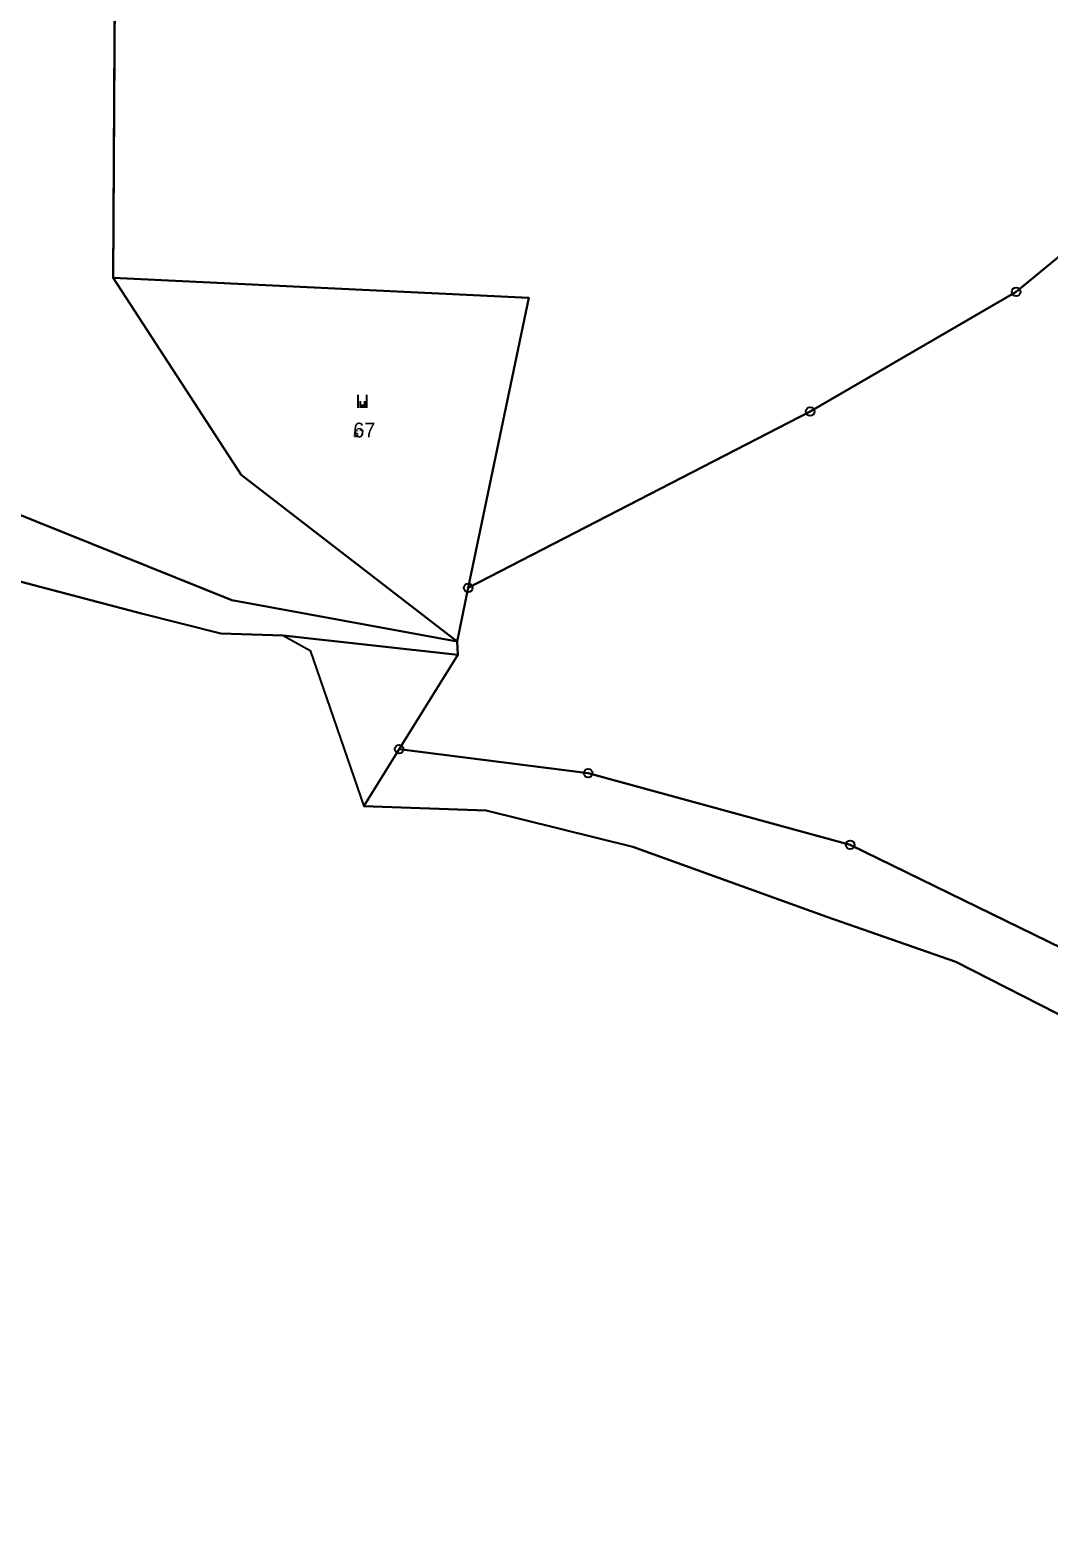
# Model space of a CAD drawing. Extents: x -759873 to -758487, y -975024 to -973516.
# Drawn here: x -759264.7 to -759147.2, y -974042.3 to -973868.5 of the extents above; entities that cross this region are included whole.
import ezdxf

# ---------------------------------------------------------------- set-up
doc = ezdxf.new("R2010")
doc.units = 0
for name, color, linetype in [('KAT_02_hranice parcel', 7, 'Continuous'), ('KAT_03_1000_čísla parcelní', 7, 'Continuous'), ('KAT_03_250_čísla parcelní', 7, 'Continuous'), ('KAT_03_500_čísla parcelní', 7, 'Continuous'), ('KAT_04_vnitřní kresba', 7, 'Continuous'), ('KAT_05_1000_značky kultur', 7, 'Continuous'), ('KAT_05_250_značky kultur', 7, 'Continuous'), ('KAT_05_500_značky kultur', 7, 'Continuous'), ('KAT_11_značky bodu BP', 7, 'Continuous'), ('KAT_14_plocha_pozemek', 7, 'Continuous')]:
    doc.layers.add(name, color=color, linetype=linetype)

msp = doc.modelspace()

# ---------------------------------------------------------------- linework, layer by layer
at = {"layer": 'KAT_02_hranice parcel'}
for p, q in [((-759254.61, -973807.34), (-759255.09, -973897.06)), ((-759214.16, -973932.79), (-759215.45, -973938.97)), ((-759215.35, -973940.53), (-759215.45, -973938.97)), ((-759222.12, -973951.41), (-759215.35, -973940.53))]:
    msp.add_line(p, q, dxfattribs=at)
for points in [[(-759214.16, -973932.79), (-759174.76, -973912.48), (-759151.02, -973898.66), (-759127.03, -973878.91), (-759116.12, -973855.51), (-759109.12, -973841.59), (-759101.89, -973841.44)], [(-759255.09, -973897.06), (-759207.19, -973899.35), (-759214.16, -973932.79)], [(-759255.09, -973897.06), (-759240.34, -973919.77), (-759215.45, -973938.97)], [(-759215.45, -973938.97), (-759241.41, -973934.23), (-759267.19, -973923.85), (-759287.59, -973930.1), (-759312.75, -973942.6), (-759338.1, -973953.37), (-759369.12, -973969.2)], [(-759215.35, -973940.53), (-759235.49, -973938.28), (-759242.67, -973938.05), (-759251.82, -973935.76), (-759267.17, -973931.74), (-759285.67, -973935.81)], [(-759144.41, -973982.83), (-759157.97, -973975.94), (-759172.81, -973970.74), (-759195.19, -973962.67), (-759212.08, -973958.48), (-759226.19, -973957.97), (-759222.12, -973951.41)], [(-759010.79, -974116.64), (-758984.12, -974076.91), (-758981.87, -974073.52), (-759005.52, -974045.86), (-759035.8, -974028.84), (-759039.41, -974027.03), (-759102.52, -973997.93), (-759142.44, -973975.96), (-759170.14, -973962.42), (-759200.34, -973954.18), (-759222.12, -973951.41)]]:
    msp.add_lwpolyline(points, dxfattribs=at)
at = {"layer": 'KAT_04_vnitřní kresba'}
for p, q in [((-759235.49, -973938.28), (-759232.38, -973940.03)), ((-759232.38, -973940.03), (-759226.19, -973957.97))]:
    msp.add_line(p, q, dxfattribs=at)
at = {"layer": 'KAT_05_1000_značky kultur'}
for p, q in [((-759226.85, -973912.04), (-759226.85, -973910.54)), ((-759225.85, -973912.04), (-759225.85, -973910.54))]:
    msp.add_line(p, q, dxfattribs=at)
at = {"layer": 'KAT_05_250_značky kultur'}
for p, q in [((-759226.47, -973912.04), (-759226.47, -973911.67)), ((-759226.22, -973912.04), (-759226.22, -973911.67))]:
    msp.add_line(p, q, dxfattribs=at)
at = {"layer": 'KAT_05_500_značky kultur'}
for p, q in [((-759226.6, -973912.04), (-759226.6, -973911.29)), ((-759226.09, -973912.04), (-759226.09, -973911.29))]:
    msp.add_line(p, q, dxfattribs=at)
at = {"layer": 'KAT_11_značky bodu BP'}
for centre, radius in [((-759151.02, -973898.66), 0.5), ((-759151.02, -973898.66), 0.0303), ((-759174.76, -973912.48), 0.5), ((-759174.76, -973912.48), 0.0303), ((-759214.16, -973932.79), 0.5), ((-759214.16, -973932.79), 0.0303), ((-759222.12, -973951.41), 0.5), ((-759222.12, -973951.41), 0.0303), ((-759200.34, -973954.18), 0.5), ((-759200.34, -973954.18), 0.0303), ((-759170.14, -973962.42), 0.5), ((-759170.14, -973962.42), 0.0303)]:
    msp.add_circle(centre, radius, dxfattribs=at)
at = {"layer": 'KAT_14_plocha_pozemek'}
for points in [[(-759127.03, -973878.91), (-759116.12, -973855.51), (-759109.12, -973841.59), (-759101.89, -973841.44), (-759129.79, -973816.86), (-759149.66, -973803.93), (-759175.81, -973793.8), (-759184.38, -973792.55), (-759202.92, -973794.85), (-759254.61, -973807.34), (-759255.09, -973897.06), (-759207.19, -973899.35), (-759214.16, -973932.79), (-759174.76, -973912.48), (-759151.02, -973898.66)], [(-759369.19, -973966.69), (-759369.12, -973969.2), (-759338.1, -973953.37), (-759312.75, -973942.6), (-759287.59, -973930.1), (-759267.19, -973923.85), (-759241.41, -973934.23), (-759215.45, -973938.97), (-759240.34, -973919.77), (-759255.09, -973897.06), (-759254.61, -973807.34), (-759283.55, -973817.84), (-759339.38, -973884.34), (-759362.29, -973932.23), (-759374.15, -973969.49)], [(-759240.34, -973919.77), (-759215.45, -973938.97), (-759214.16, -973932.79), (-759207.19, -973899.35), (-759255.09, -973897.06)], [(-759312.75, -973942.6), (-759338.1, -973953.37), (-759369.12, -973969.2), (-759369.08, -973970.45), (-759362.32, -973968.45), (-759336.73, -973957.71), (-759310.15, -973946.83), (-759285.67, -973935.81), (-759267.17, -973931.74), (-759251.82, -973935.76), (-759242.67, -973938.05), (-759235.49, -973938.28), (-759215.35, -973940.53), (-759215.45, -973938.97), (-759241.41, -973934.23), (-759267.19, -973923.85), (-759287.59, -973930.1)]]:
    msp.add_lwpolyline(points, close=True, dxfattribs=at)
for points in [[(-759116.12, -973855.51), (-759127.03, -973878.91), (-759151.02, -973898.66), (-759174.76, -973912.48), (-759214.16, -973932.79), (-759215.45, -973938.97), (-759215.35, -973940.53), (-759222.12, -973951.41), (-759200.34, -973954.18), (-759170.14, -973962.42), (-759142.44, -973975.96), (-759102.52, -973997.93), (-759039.41, -974027.03), (-759035.8, -974028.84), (-759005.52, -974045.86)], [(-759050.16, -974065.96), (-759040.87, -974035.88), (-759051.01, -974030.56), (-759061.34, -974025.15), (-759076.61, -974019.54), (-759116.39, -973998.92), (-759144.41, -973982.83), (-759157.97, -973975.94), (-759172.81, -973970.74), (-759195.19, -973962.67), (-759212.08, -973958.48), (-759226.19, -973957.97), (-759222.12, -973951.41), (-759215.35, -973940.53), (-759235.49, -973938.28), (-759242.67, -973938.05), (-759251.82, -973935.76), (-759267.17, -973931.74), (-759285.67, -973935.81), (-759275, -974011.6), (-759272.31, -974023.19), (-759274.89, -974041.82), (-759275.27, -974052.69)], [(-759005.52, -974045.86), (-759035.8, -974028.84), (-759039.41, -974027.03), (-759102.52, -973997.93), (-759142.44, -973975.96), (-759170.14, -973962.42), (-759200.34, -973954.18), (-759222.12, -973951.41), (-759226.19, -973957.97), (-759212.08, -973958.48), (-759195.19, -973962.67), (-759172.81, -973970.74), (-759157.97, -973975.94), (-759144.41, -973982.83), (-759097.1, -974003.17), (-759073.42, -974013.63), (-759056.71, -974022.34), (-759039.28, -974030.61), (-759035.77, -974032.46), (-759045.18, -974065.84)]]:
    msp.add_lwpolyline(points, dxfattribs=at)

# ---------------------------------------------------------------- texts
at = {"layer": 'KAT_03_1000_čísla parcelní'}
msp.add_text('67', height=1.7, dxfattribs=at).set_placement((-759227.41, -973915.45))
at = {"layer": 'KAT_03_250_čísla parcelní'}
msp.add_text('67', height=0.425, dxfattribs=at).set_placement((-759227.41, -973915.45))
at = {"layer": 'KAT_03_500_čísla parcelní'}
msp.add_text('67', height=0.85, dxfattribs=at).set_placement((-759227.41, -973915.45))

doc.saveas('drawing.dxf')
